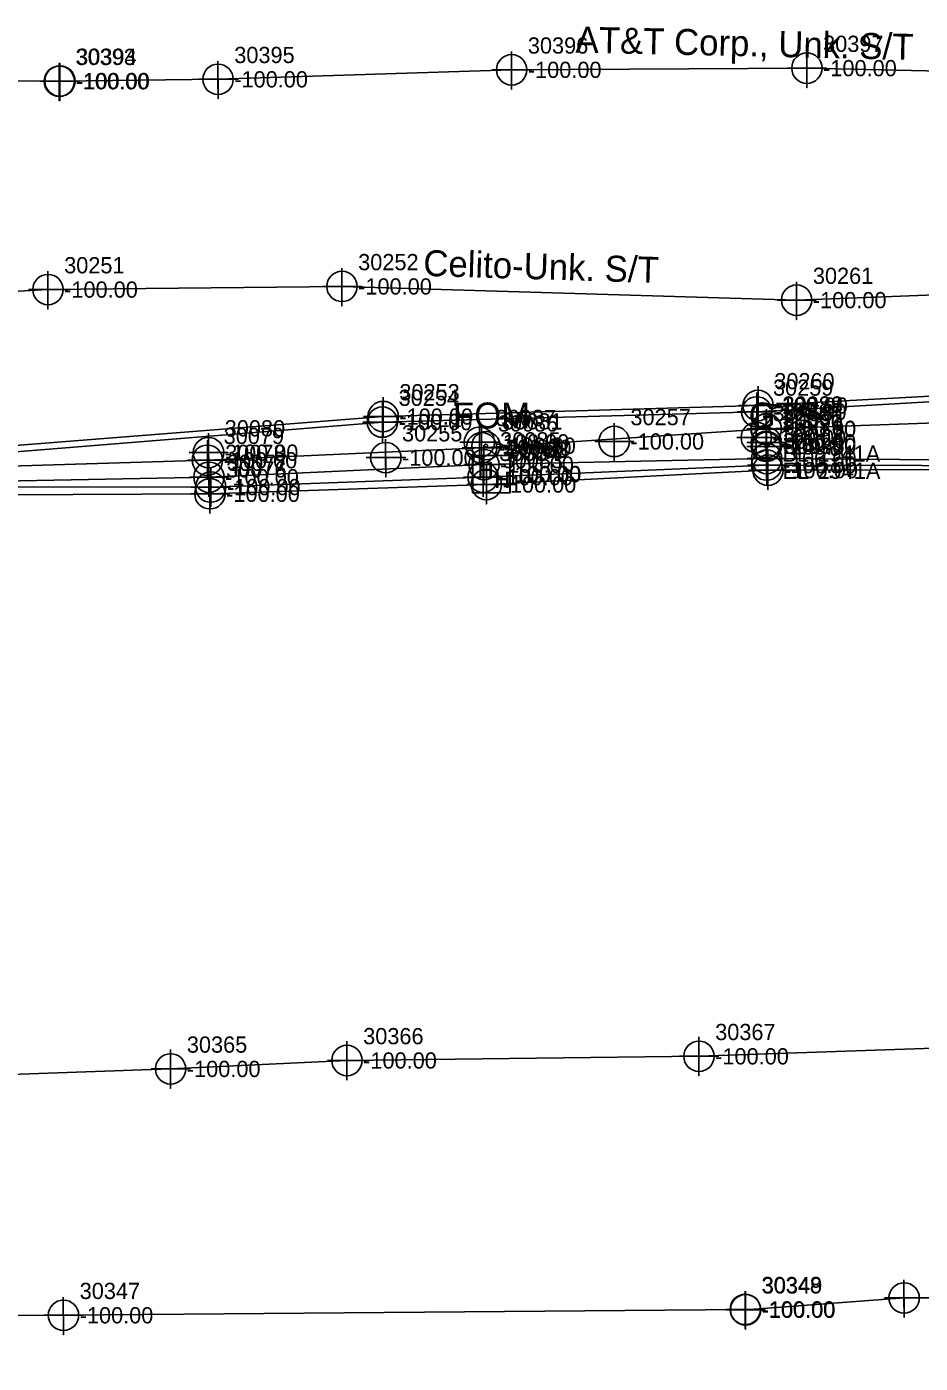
# Model space of a CAD drawing. Extents: x 2083698 to 2094313, y 743246 to 752873.
# Drawn here: x 2089203.2 to 2089340.7, y 744609.2 to 744815.1 of the extents above; entities that cross this region are included whole.
import ezdxf

# ---------------------------------------------------------------- set-up
doc = ezdxf.new("R2010")
doc.units = 0
for name, color, linetype in [('COGO Default Chain', 7, 'Continuous'), ('COGO Default Curve', 7, 'Continuous'), ('COGO Default Parcel', 7, 'Continuous'), ('COGO Default Point Number', 7, 'Continuous'), ('Default Symbol CELL', 7, 'Continuous'), ('Default Symbol Cogo Number', 7, 'Continuous'), ('Exist Property Corner Cogo Comment', 7, 'Continuous'), ('Exist Property Deed Book Text', 7, 'Continuous'), ('Exist Property Line', 7, 'Continuous'), ('Exist Property Line Leader', 7, 'Continuous'), ('Exist Property Owner Text', 7, 'Continuous'), ('Exist Right of Way Easement Line', 7, 'Continuous'), ('Exist Right of Way Line', 7, 'Continuous'), ('Exist Right of Way Line Leader', 7, 'Continuous'), ('Exist Right of Way Line Text', 7, 'Continuous'), ('Exist Utilities Gas UG Line SUE LOS B', 7, 'Continuous'), ('Exist Utilities Other Located Object CELL', 7, 'Continuous'), ('Exist Utilities Other Located Object Text', 7, 'Continuous'), ('Exist Utilities Telephone UG Conduit SUE LOS B', 7, 'Continuous'), ('Exist Utilities Telephone UG Conduit SUE LOS B Text', 7, 'Continuous'), ('Exist Utilities TV UG Cable SUE LOS B', 7, 'Continuous'), ('Exist Utilities Water UG Line SUE LOS B', 7, 'Continuous'), ('Old_Level_20', 7, 'Continuous'), ('Scratch_Level_0', 7, 'Continuous'), ('Scratch_Level_2', 7, 'Continuous')]:
    doc.layers.add(name, color=color, linetype=linetype)

msp = doc.modelspace()

# ---------------------------------------------------------------- linework, layer by layer
at = {"layer": 'COGO Default Curve'}
for points in [[(2089314.01, 744753.13), (2089320.01, 744753.13), (2089317.01, 744753.13), (2089317.01, 744756.13), (2089317.01, 744750.13)], [(2089314.04, 744753.19), (2089320.04, 744753.19), (2089317.04, 744753.19), (2089317.04, 744756.19), (2089317.04, 744750.19)], [(2089270.19, 744750.26), (2089276.19, 744750.26), (2089273.19, 744750.26), (2089273.19, 744753.26), (2089273.19, 744747.26)], [(2089314.04, 744750.48), (2089320.04, 744750.48), (2089317.04, 744750.48), (2089317.04, 744753.48), (2089317.04, 744747.48)], [(2089227.97, 744748.35), (2089233.97, 744748.35), (2089230.97, 744748.35), (2089230.97, 744751.35), (2089230.97, 744745.35)]]:
    msp.add_lwpolyline(points, dxfattribs=at)
for centre in [(2089317.01, 744753.13), (2089317.04, 744753.19), (2089273.19, 744750.26), (2089317.04, 744750.48), (2089230.97, 744748.35)]:
    msp.add_circle(centre, 2.34, dxfattribs=at)
at = {"layer": 'COGO Default Point Number'}
for points in [[(2089272.85, 744754.11), (2089272.85, 744748.11), (2089272.85, 744751.11), (2089275.85, 744751.11), (2089269.85, 744751.11)], [(2089317.02, 744754.1), (2089317.02, 744748.1), (2089317.02, 744751.1), (2089320.02, 744751.1), (2089314.02, 744751.1)], [(2089231.14, 744752.52), (2089231.14, 744746.52), (2089231.14, 744749.52), (2089234.14, 744749.52), (2089228.14, 744749.52)], [(2089306.66, 744659.52), (2089306.66, 744653.52), (2089306.66, 744656.52), (2089309.66, 744656.52), (2089303.66, 744656.52)], [(2089225.31, 744657.58), (2089225.31, 744651.58), (2089225.31, 744654.58), (2089228.31, 744654.58), (2089222.31, 744654.58)], [(2089252.46, 744658.88), (2089252.46, 744652.88), (2089252.46, 744655.88), (2089255.46, 744655.88), (2089249.46, 744655.88)]]:
    msp.add_lwpolyline(points, dxfattribs=at)
for centre in [(2089231.14, 744749.52), (2089272.85, 744751.11), (2089317.02, 744751.1), (2089225.31, 744654.58), (2089252.46, 744655.88), (2089306.66, 744656.52)]:
    msp.add_circle(centre, 2.34, dxfattribs=at)
at = {"layer": 'Exist Property Deed Book Text'}
for p, q in [((2089274.65, 744746.19), (2089274.65, 744746.19)), ((2089274.72, 744746.22), (2089274.72, 744746.22))]:
    msp.add_line(p, q, dxfattribs=at)
for points in [[(2089271.78, 744743.31), (2089277.53, 744743.31), (2089277.53, 744749.06), (2089271.78, 744749.06), (2089271.78, 744743.31)], [(2089271.85, 744743.34), (2089277.6, 744743.34), (2089277.6, 744749.09), (2089271.85, 744749.09), (2089271.85, 744743.34)]]:
    msp.add_lwpolyline(points, dxfattribs=at)
at = {"layer": 'Exist Property Line Leader'}
for points in [[(2089258.03, 744758.08), (2089258.03, 744752.08), (2089258.03, 744755.08), (2089261.03, 744755.08), (2089255.03, 744755.08)], [(2089315.56, 744758.79), (2089315.56, 744752.79), (2089315.56, 744755.79), (2089318.56, 744755.79), (2089312.56, 744755.79)], [(2089315.76, 744759.78), (2089315.76, 744753.78), (2089315.76, 744756.78), (2089318.76, 744756.78), (2089312.76, 744756.78)], [(2089257.91, 744757.22), (2089257.91, 744751.22), (2089257.91, 744754.22), (2089260.91, 744754.22), (2089254.91, 744754.22)], [(2089273.55, 744750.67), (2089273.55, 744744.67), (2089273.55, 744747.67), (2089276.55, 744747.67), (2089270.55, 744747.67)], [(2089317.08, 744751.6), (2089317.08, 744745.6), (2089317.08, 744748.6), (2089320.08, 744748.6), (2089314.08, 744748.6)], [(2089317.11, 744750.61), (2089317.11, 744744.61), (2089317.11, 744747.61), (2089320.11, 744747.61), (2089314.11, 744747.61)], [(2089317.29, 744749.82), (2089317.29, 744743.82), (2089317.29, 744746.82), (2089320.29, 744746.82), (2089314.29, 744746.82)], [(2089231.21, 744748.73), (2089231.21, 744742.73), (2089231.21, 744745.73), (2089234.21, 744745.73), (2089228.21, 744745.73)], [(2089273.41, 744748.73), (2089273.41, 744742.73), (2089273.41, 744745.73), (2089276.41, 744745.73), (2089270.41, 744745.73)], [(2089273.93, 744747.61), (2089273.93, 744741.61), (2089273.93, 744744.61), (2089276.93, 744744.61), (2089270.93, 744744.61)], [(2089231.36, 744746.18), (2089231.36, 744740.18), (2089231.36, 744743.18), (2089234.36, 744743.18), (2089228.36, 744743.18)], [(2089231.48, 744747.21), (2089231.48, 744741.21), (2089231.48, 744744.21), (2089234.48, 744744.21), (2089228.48, 744744.21)]]:
    msp.add_lwpolyline(points, dxfattribs=at)
for centre in [(2089315.56, 744755.79), (2089315.76, 744756.78), (2089257.91, 744754.22), (2089258.03, 744755.08), (2089273.55, 744747.67), (2089317.08, 744748.6), (2089317.11, 744747.61), (2089231.21, 744745.73), (2089273.41, 744745.73), (2089317.29, 744746.82), (2089231.36, 744743.18), (2089231.48, 744744.21), (2089273.93, 744744.61)]:
    msp.add_circle(centre, 2.34, dxfattribs=at)
at = {"layer": 'Exist Right of Way Line Text'}
for points in [[(2089323.25, 744811.57), (2089323.28, 744805.75), (2089323.26, 744808.75), (2089326.28, 744808.75), (2089320.28, 744808.75)], [(2089208.13, 744809.54), (2089208.17, 744803.73), (2089208.15, 744806.73), (2089211.17, 744806.73), (2089205.17, 744806.73)], [(2089208.24, 744809.58), (2089208.27, 744803.76), (2089208.26, 744806.76), (2089211.27, 744806.76), (2089205.27, 744806.76)], [(2089232.58, 744809.84), (2089232.61, 744804.03), (2089232.59, 744807.03), (2089235.61, 744807.03), (2089229.61, 744807.03)], [(2089277.79, 744811.31), (2089277.82, 744805.49), (2089277.81, 744808.49), (2089280.82, 744808.49), (2089274.82, 744808.49)], [(2089206.39, 744777.46), (2089206.42, 744771.64), (2089206.41, 744774.64), (2089209.42, 744774.64), (2089203.42, 744774.64)], [(2089251.66, 744777.94), (2089251.69, 744772.12), (2089251.67, 744775.12), (2089254.69, 744775.12), (2089248.69, 744775.12)], [(2089321.67, 744775.82), (2089321.7, 744770.01), (2089321.69, 744773.01), (2089324.7, 744773.01), (2089318.7, 744773.01)], [(2089293.58, 744754.05), (2089293.61, 744748.24), (2089293.59, 744751.24), (2089296.61, 744751.24), (2089290.61, 744751.24)], [(2089315.46, 744754.66), (2089315.49, 744748.85), (2089315.47, 744751.85), (2089318.49, 744751.85), (2089312.49, 744751.85)], [(2089258.41, 744751.57), (2089258.44, 744745.75), (2089258.42, 744748.75), (2089261.44, 744748.75), (2089255.44, 744748.75)], [(2089338.22, 744622.11), (2089338.25, 744616.3), (2089338.23, 744619.3), (2089341.25, 744619.3), (2089335.25, 744619.3)], [(2089313.76, 744620.36), (2089313.79, 744614.54), (2089313.78, 744617.54), (2089316.79, 744617.54), (2089310.79, 744617.54)], [(2089313.82, 744620.29), (2089313.85, 744614.47), (2089313.83, 744617.47), (2089316.85, 744617.47), (2089310.85, 744617.47)], [(2089208.78, 744619.44), (2089208.81, 744613.63), (2089208.79, 744616.63), (2089211.81, 744616.63), (2089205.81, 744616.63)]]:
    msp.add_lwpolyline(points, dxfattribs=at)
for centre in [(2089232.61, 744807.03), (2089277.82, 744808.49), (2089323.28, 744808.75), (2089208.17, 744806.73), (2089208.27, 744806.76), (2089206.42, 744774.64), (2089251.69, 744775.12), (2089321.7, 744773.01), (2089315.49, 744751.85), (2089293.61, 744751.24), (2089258.44, 744748.75), (2089313.79, 744617.54), (2089338.25, 744619.3), (2089208.81, 744616.63), (2089313.85, 744617.47)]:
    msp.add_circle(centre, 2.34, dxfattribs=at)
at = {"layer": 'Exist Utilities Gas UG Line SUE LOS B'}
msp.add_line((2089317.01, 744753.13), (2089317.04, 744750.48), dxfattribs=at)
msp.add_lwpolyline([(2089188.64, 744747.1), (2089230.97, 744748.35), (2089273.19, 744750.26), (2089317.04, 744753.19), (2089364.98, 744754.89), (2089387.44, 744755.62), (2089404.76, 744756.19), (2089425.01, 744756.79), (2089443.27, 744757.04), (2089483.06, 744758.61), (2089527.53, 744760.45), (2089553.61, 744761.17), (2089595.23, 744761.81), (2089636.84, 744760.15), (2089681.8, 744758.88), (2089727.57, 744756.98), (2089768.51, 744753.63)], dxfattribs=at)
at = {"layer": 'Exist Utilities Other Located Object CELL'}
for centre, radius in [((2089273.86, 744750.58), 2.18), ((2089317.05, 744750.47), 2.18), ((2089273.86, 744750.58), 0.24), ((2089317.05, 744750.47), 0.24)]:
    msp.add_circle(centre, radius, dxfattribs=at)
at = {"layer": 'Exist Utilities Telephone UG Conduit SUE LOS B'}
for points in [[(2089061.62, 744791.75), (2089067.88, 744793.23), (2089088.91, 744796.69), (2089115.45, 744799.75), (2089135.45, 744804.3), (2089163.31, 744806.79), (2089208.17, 744806.73), (2089208.27, 744806.76), (2089232.61, 744807.03), (2089277.82, 744808.49), (2089323.28, 744808.75), (2089348.6, 744808.2), (2089372.34, 744807.42)], [(2089145.2, 744771.18), (2089206.42, 744774.64), (2089251.69, 744775.12), (2089321.7, 744773.01), (2089366.99, 744774.73), (2089407.11, 744775.19), (2089438.31, 744775.33), (2089485.01, 744776.05), (2089525.37, 744777.9), (2089574.4, 744778.04), (2089607.37, 744778.88), (2089668.76, 744778.9), (2089739.62, 744775.11), (2089794.23, 744770.71)], [(2089155.86, 744616.56), (2089208.81, 744616.63), (2089313.79, 744617.54), (2089313.85, 744617.47), (2089338.25, 744619.3), (2089389.63, 744619.3), (2089408.85, 744619.19), (2089454.75, 744619.43), (2089478.31, 744618.6), (2089521.57, 744619.63), (2089571.18, 744617.74), (2089588.86, 744618.02), (2089632.51, 744615.38), (2089673.98, 744613.02), (2089692.08, 744612.74), (2089765.9, 744609.24)]]:
    msp.add_lwpolyline(points, dxfattribs=at)
at = {"layer": 'Exist Utilities TV UG Cable SUE LOS B'}
for points in [[(2089188.75, 744744.93), (2089231.21, 744745.73), (2089273.55, 744747.67), (2089317.08, 744748.6), (2089364.87, 744748.25), (2089387.88, 744750.84), (2089405.09, 744750.49), (2089414.3, 744755), (2089437.94, 744768.54), (2089482.55, 744772.05), (2089527.16, 744774.21), (2089552.76, 744774.77), (2089591.94, 744775.4), (2089636.91, 744774.94), (2089688.64, 744772.79), (2089726.6, 744771.68), (2089764.39, 744770.54)], [(2089189.01, 744744.25), (2089231.48, 744744.21), (2089273.41, 744745.73), (2089317.11, 744747.61), (2089364.92, 744747.5), (2089387.99, 744749.19), (2089405.31, 744749.3), (2089414.63, 744754.62), (2089438.38, 744768.09), (2089482.53, 744771.23), (2089527.3, 744773.43), (2089552.73, 744773.44), (2089592.1, 744774.64), (2089636.89, 744774.29), (2089688.95, 744771.93), (2089726.77, 744770.46), (2089764.51, 744769.72)], [(2088702.04, 744692.87), (2088747.83, 744702.02), (2088807.09, 744711.57), (2088863.56, 744720.83), (2088917.68, 744727.61), (2088958.28, 744732.15), (2089001.43, 744738.44), (2089033.44, 744742.83), (2089063.64, 744746.68), (2089098.1, 744749.39), (2089140.66, 744750.1), (2089171.19, 744747.82), (2089189.01, 744749.64), (2089258.03, 744755.08), (2089315.76, 744756.78), (2089365.87, 744759.51), (2089403.13, 744760.57), (2089434.85, 744761.3)], [(2088702.46, 744691.66), (2088747.9, 744701.08), (2088807.16, 744710.81), (2088863.81, 744719.73), (2088917.8, 744726.57), (2088958.35, 744731.03), (2089001.3, 744737.54), (2089033.45, 744741.69), (2089063.64, 744745.88), (2089098.22, 744748.67), (2089140.71, 744748.82), (2089171.23, 744747.79), (2089188.81, 744748.61), (2089257.91, 744754.22), (2089315.56, 744755.79), (2089365.89, 744758.74), (2089403.23, 744759.85), (2089434.88, 744760.17)], [(2088703.78, 744687.07), (2088731.41, 744691.38), (2088759.52, 744695.04), (2088784.54, 744697.84), (2088808.59, 744700.07), (2088866.55, 744709.27), (2088919.81, 744716.01), (2088960.48, 744720.38), (2088999.19, 744725.11), (2089036.36, 744727.95), (2089087.5, 744732.4), (2089099.66, 744734.5), (2089122.23, 744736.49), (2089157.51, 744740.67), (2089189.18, 744742.99), (2089231.36, 744743.18), (2089273.93, 744744.61), (2089317.29, 744746.82), (2089364.91, 744746.95), (2089388.1, 744748.39), (2089405.44, 744748.61), (2089438.07, 744752.83), (2089439.47, 744753.63), (2089439.15, 744759.31)]]:
    msp.add_lwpolyline(points, dxfattribs=at)
at = {"layer": 'Exist Utilities Water UG Line SUE LOS B'}
msp.add_lwpolyline([(2089173.12, 744652.76), (2089225.31, 744654.58), (2089252.46, 744655.88), (2089306.66, 744656.52), (2089357.98, 744658.3), (2089395.88, 744658.67), (2089431.64, 744659.7), (2089481.06, 744660.73), (2089530.4, 744660.37), (2089602.26, 744658.77), (2089602.3, 744658.72), (2089614.15, 744658.16), (2089668.46, 744656.13), (2089668.53, 744656.22), (2089713.78, 744654.4), (2089759.79, 744652.4)], dxfattribs=at)

# ---------------------------------------------------------------- texts
at = {"layer": 'COGO Default Chain'}
for p in [(2089319.51, 744751.88), (2089319.54, 744751.94), (2089319.54, 744749.23), (2089233.47, 744747.1), (2089275.69, 744749.01)]:
    msp.add_text('-100.00', height=2.5, dxfattribs=at).set_placement(p)
at = {"layer": 'COGO Default Parcel'}
for s, p in [('30081', (2089276.36, 744753.08)), ('30091', (2089319.55, 744752.97))]:
    msp.add_text(s, height=2.5, dxfattribs=at).set_placement(p)
at = {"layer": 'Default Symbol CELL'}
for s, p in [('30253', (2089260.53, 744757.58)), ('30259', (2089318.06, 744758.29)), ('30260', (2089318.26, 744759.28)), ('30254', (2089260.41, 744756.72)), ('30085', (2089276.05, 744750.17)), ('30093', (2089319.58, 744751.1)), ('30094', (2089319.61, 744750.11)), ('30095', (2089319.79, 744749.32)), ('30078', (2089233.71, 744748.23)), ('30084', (2089275.91, 744748.23)), ('30083', (2089276.43, 744747.11)), ('30076', (2089233.86, 744745.68)), ('30077', (2089233.98, 744746.71))]:
    msp.add_text(s, height=2.5, dxfattribs=at).set_placement(p)
at = {"layer": 'Default Symbol Cogo Number'}
for p in [(2089318.26, 744755.53), (2089260.53, 744753.83), (2089318.06, 744754.54), (2089260.41, 744752.97), (2089319.58, 744747.35), (2089276.05, 744746.42), (2089319.61, 744746.36), (2089319.79, 744745.57), (2089233.71, 744744.48), (2089233.98, 744742.96), (2089275.91, 744744.48), (2089276.43, 744743.36), (2089233.86, 744741.93)]:
    msp.add_text('-100.00', height=2.5, dxfattribs=at).set_placement(p)
at = {"layer": 'Exist Property Corner Cogo Comment'}
for p in [(2089277.22, 744744.97), (2089277.15, 744744.94)]:
    msp.add_text('-100.00', height=2.5, dxfattribs=at).set_placement(p)
at = {"layer": 'Exist Property Deed Book Text'}
for p in [(2089272.57, 744745.54), (2089272.63, 744745.57), (2089275.14, 744744.08), (2089275.21, 744744.11)]:
    msp.add_text('H', height=2.5, dxfattribs=at).set_placement(p)
at = {"layer": 'Exist Property Line'}
for p in [(2089275.35, 744749.86), (2089319.52, 744749.85), (2089233.64, 744748.27), (2089254.96, 744654.63), (2089309.16, 744655.27), (2089227.81, 744653.33)]:
    msp.add_text('-100.00', height=2.5, dxfattribs=at).set_placement(p)
at = {"layer": 'Exist Property Owner Text'}
for s, p in [('30256', (2089277.15, 744748.69)), ('30082', (2089277.22, 744748.72))]:
    msp.add_text(s, height=2.5, dxfattribs=at).set_placement(p)
at = {"layer": 'Exist Right of Way Easement Line'}
for s, p in [('BL*2941A', (2089319.51, 744748.13)), ('EL*2941A', (2089319.54, 744745.48))]:
    msp.add_text(s, height=2.5, dxfattribs=at).set_placement(p)
at = {"layer": 'Exist Right of Way Line'}
for s, p in [('30087', (2089275.35, 744753.61)), ('30092', (2089319.52, 744753.6)), ('30080', (2089233.64, 744752.02)), ('30367', (2089309.16, 744659.02)), ('30365', (2089227.81, 744657.08)), ('30366', (2089254.96, 744658.38))]:
    msp.add_text(s, height=2.5, dxfattribs=at).set_placement(p)
at = {"layer": 'Exist Right of Way Line Leader'}
for s, p in [('30396', (2089280.32, 744810.99)), ('30397', (2089325.78, 744811.25)), ('30393', (2089210.67, 744809.23)), ('30394', (2089210.77, 744809.26)), ('30395', (2089235.11, 744809.53)), ('30251', (2089208.92, 744777.14)), ('30252', (2089254.19, 744777.62)), ('30261', (2089324.2, 744775.51)), ('30257', (2089296.11, 744753.74)), ('30258', (2089317.99, 744754.35)), ('30255', (2089260.94, 744751.25)), ('30348', (2089316.29, 744620.04)), ('30349', (2089316.35, 744619.97)), ('30347', (2089211.31, 744619.13))]:
    msp.add_text(s, height=2.5, dxfattribs=at).set_placement(p)
at = {"layer": 'Exist Utilities Other Located Object Text'}
for s, p in [('FOM', (2089268.78, 744753.24)), ('GTS', (2089314.31, 744753.24))]:
    msp.add_text(s, height=4, dxfattribs=at).set_placement(p)
at = {"layer": 'Exist Utilities Telephone UG Conduit SUE LOS B Text'}
for s, rotation, p in [('AT&T Corp., Unk. S/T', 358.7392, (2089287.64, 744811.16)), ('Celito-Unk. S/T', 358.2687, (2089264.17, 744776.75))]:
    msp.add_text(s, height=4, rotation=rotation, dxfattribs=at).set_placement(p)
at = {"layer": 'Old_Level_20'}
for s, p in [('30089', (2089319.51, 744755.63)), ('30088', (2089319.54, 744755.69)), ('30086', (2089275.69, 744752.76)), ('30090', (2089319.54, 744752.98)), ('30079', (2089233.47, 744750.85))]:
    msp.add_text(s, height=2.5, dxfattribs=at).set_placement(p)
at = {"layer": 'Scratch_Level_0'}
for p in [(2089276.36, 744749.33), (2089319.55, 744749.22)]:
    msp.add_text('-100.00', height=2.5, dxfattribs=at).set_placement(p)
at = {"layer": 'Scratch_Level_2'}
for p in [(2089280.32, 744807.24), (2089325.78, 744807.5), (2089210.67, 744805.48), (2089210.77, 744805.51), (2089235.11, 744805.78), (2089254.19, 744773.87), (2089208.92, 744773.39), (2089324.2, 744771.76), (2089296.11, 744749.99), (2089317.99, 744750.6), (2089260.94, 744747.5), (2089211.31, 744615.38), (2089316.29, 744616.29), (2089316.35, 744616.22)]:
    msp.add_text('-100.00', height=2.5, dxfattribs=at).set_placement(p)

doc.saveas('drawing.dxf')
